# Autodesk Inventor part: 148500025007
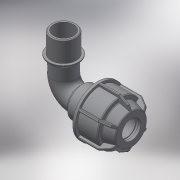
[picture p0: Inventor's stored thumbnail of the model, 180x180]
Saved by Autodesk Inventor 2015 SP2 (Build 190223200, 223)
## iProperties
Created: 2017-08
Part Number: 148500025007
Material: Generic
Description: PLASSON L.14 90° ELBOW MALE ADAPTOR (SILVER) 25-3/4"
Document SubType Name: Modeling
Designer: KIM
Density: 1 g/cm^3
Appearance: Default
Author: KIM
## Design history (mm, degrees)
derived "148500.ipt"
feature "Solid1::148500.ipt"
feature "Solid2::148500.ipt"
tag "TaggingFeature1"
body "Solid1"
body "Solid2"
other parameters: "d1" = 25, "d2" = 47, "d4" = 15 deg, "d5" = 31.02, "d6" = 10.2366, "d16" = 25.5, "d17" = 2.35, "d24" = 2.35, "d25" = 45, "d26" = 37.5, "d27" = 2.35, "d28" = 135 deg, "d29" = 1.41, "d31" = 1.25, "d46" = 150 deg, "d49" = 2.5, "d50" = 0, "d58" = 0.75, "d61" = 360 deg, "d63" = 22.5, "d94" = 47, "d96" = 29.0851, "d97" = 18, "d98" = 21.1528, "d99" = 24.72234, "d100" = 135 deg, "d108" = 1.25, "d112" = 23.4, "d113" = 62, "d114" = 49.35, "d115" = 24.72234, "d116" = 45 deg, "d117" = 0, "d118" = 0, "d119" = 26.441, "d120" = 18, "d121" = 31.7292, "d122" = 18.9, "d123" = 1, "d_" = 25, "R_" = 26.441, "A_" = 62, "l_" = 47, "l_2" = 18, "A_1" = 47
